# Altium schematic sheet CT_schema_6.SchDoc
size 368 x 245 mm
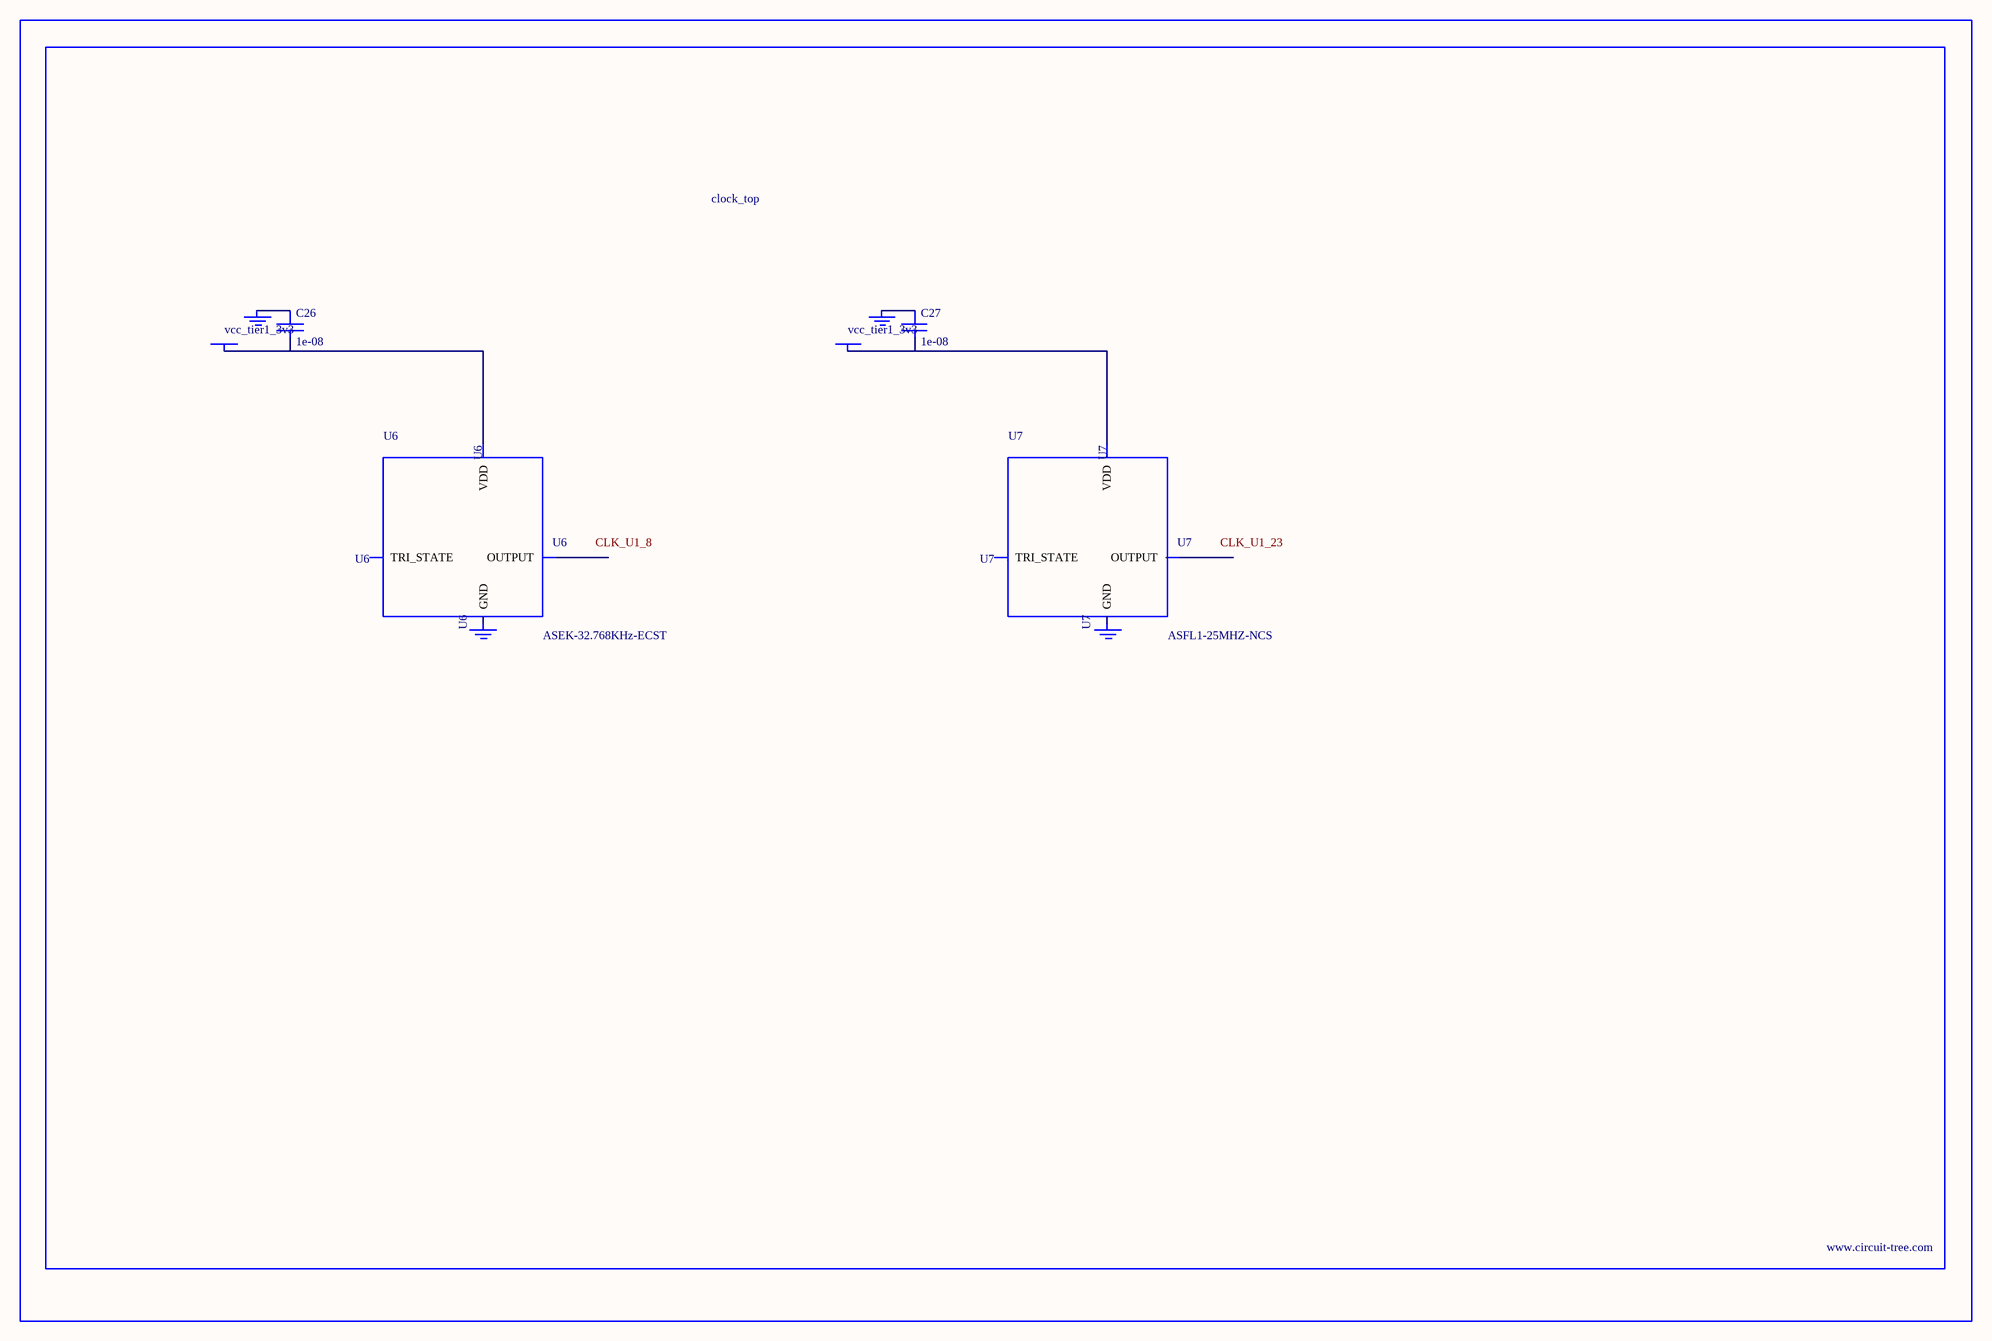
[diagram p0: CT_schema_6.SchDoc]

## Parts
BORDER5  (no value)
C26  1e-08  [C0402]
C27  1e-08  [C0402]
GND_INSTANCE_5_0  (no value)
GND_INSTANCE_5_1  (no value)
GND_INSTANCE_5_2  (no value)
GND_INSTANCE_5_3  (no value)
POWER_INSTANCE_5_0  vcc_tier1_3v3
POWER_INSTANCE_5_1  vcc_tier1_3v3
U6  ASEK-32.768KHz-ECST  [ASEK]
U7  ASFL1-25MHZ-NCS  [ASFL1]

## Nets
NetC26_1: C26.1 GND_INSTANCE_5_0.0(GND)
NetC26_2: C26.2 POWER_INSTANCE_5_0.0(PWR) U6.4(VDD)
NetC27_1: C27.1 GND_INSTANCE_5_2.0(GND)
NetC27_2: C27.2 POWER_INSTANCE_5_1.0(PWR) U7.4(VDD)

Not connected (* = marked no-connect by the designer): GND_INSTANCE_5_1 0(GND); GND_INSTANCE_5_3 0(GND); U6 1(TRI_STATE) 2(GND) 3(OUTPUT); U7 1(TRI_STATE) 2(GND) 3(OUTPUT)

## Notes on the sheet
- Labels drawn without touching a wire or pin: CLK_U1_8, CLK_U1_23

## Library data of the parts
BORDER5 = BORDER_PAGE5
C26 C27 = C0402C103K3RAC
GND_INSTANCE_5_0-GND_INSTANCE_5_3 = GND
POWER_INSTANCE_5_0 POWER_INSTANCE_5_1 = PWR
